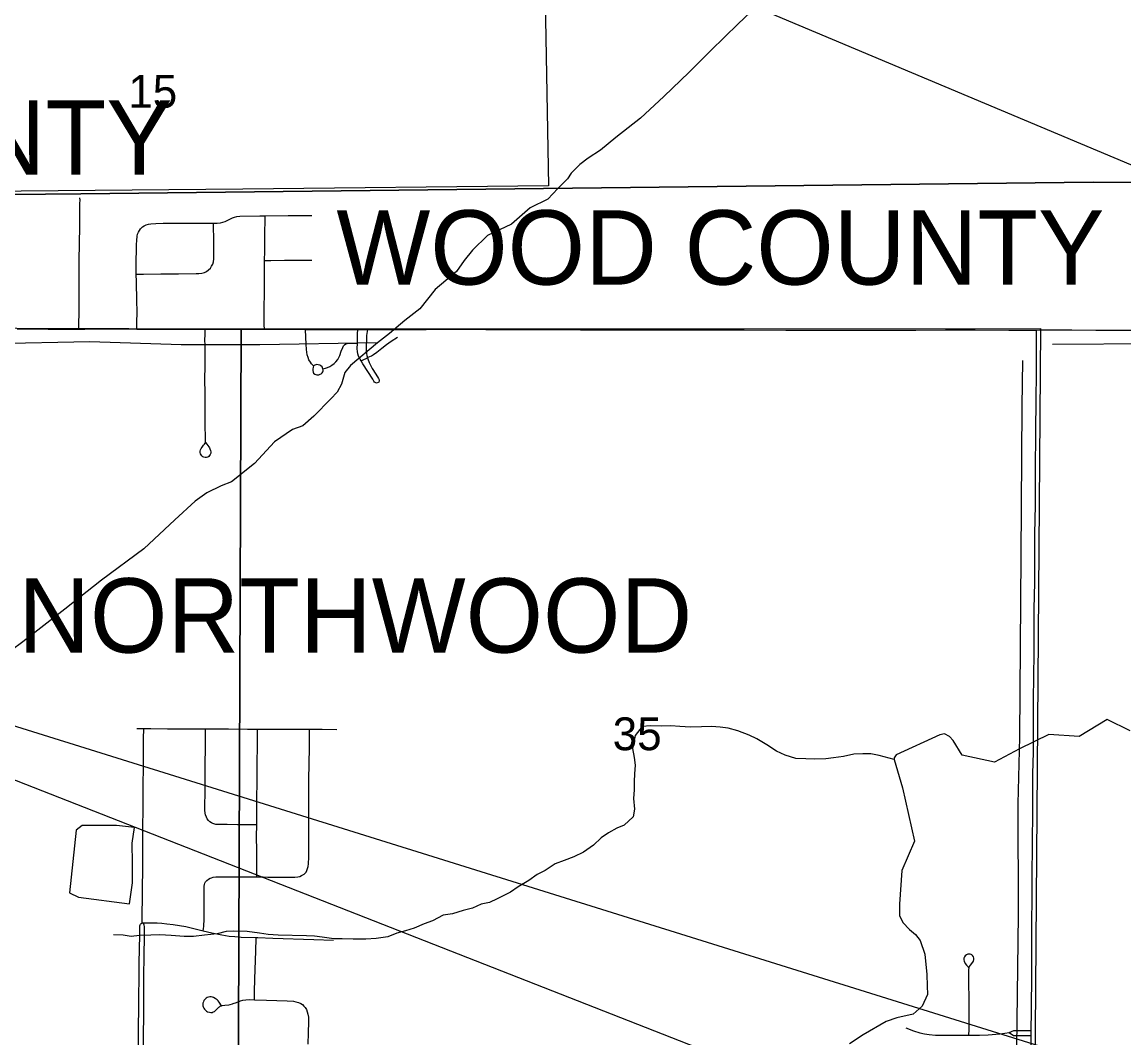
# Model space of a CAD drawing. Extents: x 0 to 40.2, y 0 to 22.
# Drawn here: x 6.486 to 7.889, y 16.354 to 17.647 of the extents above; entities that cross this region are included whole.
import ezdxf

# ---------------------------------------------------------------- set-up
doc = ezdxf.new("R2010")
doc.units = 0
for name, color, linetype in [('GM_X_City_Street', 7, 'Continuous'), ('GM_X_Corporation', 7, 'Continuous'), ('GM_X_County', 7, 'Continuous'), ('GM_X_Minor_Lake', 7, 'Continuous'), ('GM_X_Minor_Lake_Text', 7, 'Continuous'), ('GM_X_Rail_Line', 7, 'Continuous'), ('GM_X_Section', 7, 'Continuous'), ('GM_X_Unincorporated_Location', 7, 'Continuous'), ('GM_X_US_Location', 7, 'Continuous')]:
    doc.layers.add(name, color=color, linetype=linetype)

msp = doc.modelspace()

# ---------------------------------------------------------------- linework, layer by layer
at = {"layer": 'GM_X_Corporation'}
for points in [[(6.1544, 17.4248), (6.5609, 17.4286), (7.8499, 17.4434), (8.1678, 17.4407), (8.7809, 17.439), (8.9, 17.4415), (8.9, 20.9)], [(6.1544, 17.4248), (6.5609, 17.4286), (7.8499, 17.4434), (8.1678, 17.4407), (8.7809, 17.439), (8.9, 17.4415), (8.9, 20.9)], [(6.1544, 17.4248), (6.5609, 17.4286), (7.8499, 17.4434), (8.1678, 17.4407), (8.7809, 17.439), (8.9, 17.4415), (8.9, 20.9)], [(8.7738, 16.2476), (8.7739, 16.404), (8.7812, 17.2357), (8.7808, 17.2416), (8.7804, 17.2472), (8.7798, 17.254), (8.7797, 17.2579), (8.7797, 17.2625), (8.7798, 17.2656), (8.7803, 17.2689), (8.7813, 17.272), (8.7828, 17.2749), (8.7809, 17.439), (8.1678, 17.4407), (7.8499, 17.4434), (6.5609, 17.4286), (6.1544, 17.4248)], [(8.7738, 16.2476), (8.7739, 16.404), (8.7812, 17.2357), (8.7808, 17.2416), (8.7804, 17.2472), (8.7798, 17.254), (8.7797, 17.2579), (8.7797, 17.2625), (8.7798, 17.2656), (8.7803, 17.2689), (8.7813, 17.272), (8.7828, 17.2749), (8.7809, 17.439), (8.1678, 17.4407), (7.8499, 17.4434), (6.5609, 17.4286), (6.1544, 17.4248)], [(8.7738, 16.2476), (8.7739, 16.404), (8.7812, 17.2357), (8.7808, 17.2416), (8.7804, 17.2472), (8.7798, 17.254), (8.7797, 17.2579), (8.7797, 17.2625), (8.7798, 17.2656), (8.7803, 17.2689), (8.7813, 17.272), (8.7828, 17.2749), (8.7809, 17.439), (8.1678, 17.4407), (7.8499, 17.4434), (6.5609, 17.4286), (6.1544, 17.4248)]]:
    msp.add_lwpolyline(points, dxfattribs=at)
for points in [[(6.1533, 17.7006), (7.1511, 17.7217), (7.1565, 17.4389), (6.7672, 17.4346), (6.1554, 17.4291)], [(5.7644, 17.2596), (6.765, 17.2565), (6.7611, 16.2529), (5.7484, 16.2569)], [(6.765, 17.2565), (7.7827, 17.257), (7.775, 16.2496), (7.7689, 16.25), (6.7611, 16.2529)]]:
    msp.add_lwpolyline(points, close=True, dxfattribs=at)
at = {"layer": 'GM_X_Minor_Lake'}
for points in [[(7.4611, 17.7074), (7.4378, 17.6833), (7.3977, 17.645), (7.363, 17.6112), (7.3355, 17.5834), (7.303, 17.5525), (7.2736, 17.5247), (7.242, 17.5004), (7.2226, 17.4842), (7.207, 17.4741), (7.1963, 17.4659), (7.1852, 17.455), (7.1806, 17.4478), (7.1684, 17.4353)], [(7.1684, 17.4353), (7.1553, 17.4216), (7.1329, 17.4106), (7.1094, 17.3901), (7.0786, 17.3754), (7.0597, 17.3567), (7.0489, 17.3436), (7.0393, 17.3297), (7.012, 17.3066), (6.9927, 17.2819), (6.9736, 17.2674), (6.954, 17.2507), (6.9387, 17.2388), (6.9042, 17.2101), (6.8972, 17.2011), (6.8928, 17.186), (6.8874, 17.1759), (6.8793, 17.1673), (6.8574, 17.1456), (6.8436, 17.1333), (6.8303, 17.1286), (6.8073, 17.1127), (6.7819, 17.085), (6.7528, 17.0619), (6.7395, 17.0569), (6.7215, 17.0477), (6.7066, 17.0373), (6.6805, 17.0134), (6.641, 16.9765), (6.5874, 16.9364), (6.5406, 16.8996), (6.487, 16.858), (6.4422, 16.8249)], [(6.9387, 17.2388), (6.7888, 17.2363), (6.6886, 17.2364), (6.5725, 17.2401), (6.4491, 17.2376), (6.2721, 17.2393), (6.1257, 17.2394), (5.9952, 17.2411), (5.6774, 17.2432)], [(8.7602, 17.2356), (8.4984, 17.2357), (8.1515, 17.2375), (7.9283, 17.2376), (7.7978, 17.2367)], [(7.7519, 16.2738), (7.7545, 16.5105), (7.7541, 16.6516), (7.7566, 16.7366), (7.758, 16.9672), (7.7595, 17.1577), (7.7604, 17.2161)], [(7.897, 16.7449), (7.8674, 16.7591), (7.8319, 16.7376), (7.7933, 16.7402), (7.7559, 16.7218), (7.7243, 16.7049), (7.6828, 16.7139), (7.6714, 16.7323), (7.6669, 16.7376), (7.6605, 16.7408), (7.6545, 16.7394), (7.5988, 16.7141), (7.5965, 16.7103), (7.5965, 16.7084), (7.6072, 16.6722), (7.6224, 16.6041), (7.6063, 16.5668), (7.6034, 16.5239), (7.6031, 16.5095), (7.6075, 16.5007), (7.6161, 16.4919), (7.6236, 16.4853), (7.6295, 16.4776), (7.6353, 16.4604), (7.6379, 16.4346), (7.6384, 16.4198), (7.639, 16.4088), (7.632, 16.3941), (7.6208, 16.384), (7.5996, 16.3791), (7.5863, 16.3747), (7.5569, 16.3577), (7.5396, 16.3463)], [(7.5965, 16.7084), (7.5773, 16.7133), (7.5667, 16.7154), (7.5565, 16.7155), (7.5451, 16.7149), (7.5318, 16.7121), (7.5193, 16.7104), (7.5095, 16.7091), (7.4955, 16.7085), (7.4841, 16.7091), (7.4713, 16.7093), (7.4577, 16.7137), (7.4468, 16.7188), (7.4341, 16.727), (7.4217, 16.7344), (7.412, 16.7391), (7.3973, 16.7446), (7.3849, 16.7483), (7.3747, 16.7492), (7.3637, 16.7501), (7.3509, 16.7499), (7.3372, 16.7494), (7.3236, 16.7504), (7.3119, 16.7509), (7.3002, 16.7508), (7.2862, 16.751), (7.2756, 16.7504), (7.2667, 16.7388), (7.2634, 16.7221), (7.2655, 16.7107), (7.2665, 16.7008), (7.2659, 16.6898), (7.2654, 16.68), (7.2652, 16.6697), (7.2647, 16.6584), (7.2656, 16.6451), (7.2643, 16.6352), (7.2528, 16.6244), (7.2433, 16.6208), (7.2329, 16.6149), (7.2234, 16.6086), (7.2134, 16.5989), (7.2008, 16.5904), (7.1886, 16.5841), (7.1764, 16.5794), (7.165, 16.5754), (7.152, 16.5669), (7.1417, 16.5617), (7.1314, 16.5543), (7.1176, 16.5462), (7.108, 16.5391), (7.0909, 16.5307), (7.0814, 16.5263), (7.0707, 16.5238), (7.0597, 16.519), (7.0475, 16.5158), (7.0342, 16.5118), (7.0221, 16.5101), (7.0087, 16.5028), (6.9981, 16.4991), (6.9851, 16.4933), (6.9741, 16.4901), (6.9631, 16.4872), (6.9517, 16.4824), (6.9369, 16.4804), (6.9236, 16.4795), (6.9077, 16.4794), (6.8934, 16.48), (6.8828, 16.4798), (6.868, 16.4819), (6.8582, 16.4832), (6.848, 16.4837), (6.8121, 16.4843), (6.7992, 16.4853), (6.7883, 16.487), (6.7728, 16.4891), (6.7558, 16.4894), (6.746, 16.4892), (6.7346, 16.4863), (6.7183, 16.4847), (6.7042, 16.483), (6.6925, 16.4828), (6.6759, 16.4842), (6.6615, 16.4848), (6.6502, 16.4843), (6.6354, 16.4841), (6.6248, 16.4828), (6.6146, 16.4845), (6.6025, 16.485)]]:
    msp.add_lwpolyline(points, dxfattribs=at)
at = {"layer": 'GM_X_Minor_Lake_Text'}
msp.add_line((6.6268, 16.5511), (6.6266, 16.5761), dxfattribs=at)
msp.add_lwpolyline([(6.6266, 16.5761), (6.6264, 16.6015), (6.6292, 16.6216), (6.6065, 16.6241), (6.5627, 16.6243), (6.5551, 16.6183), (6.5466, 16.5383), (6.5579, 16.533), (6.6229, 16.5242), (6.6268, 16.5511)], dxfattribs=at)
at = {"layer": 'GM_X_Rail_Line'}
msp.add_line((6.7946, 17.2561), (6.8468, 17.2559), dxfattribs=at)
for points in [[(6.4797, 17.2565), (6.5194, 17.2564), (6.5582, 17.2562)], [(6.5582, 17.2562), (6.5661, 17.2562), (6.6027, 17.2566), (6.632, 17.2564)], [(6.632, 17.2564), (6.6407, 17.2563), (6.6805, 17.2564), (6.719, 17.2562)], [(6.719, 17.2562), (6.724, 17.2561), (6.7706, 17.2562), (6.7946, 17.2561)], [(6.8468, 17.2559), (6.8844, 17.2558), (6.9134, 17.2557)], [(6.9134, 17.2557), (6.9257, 17.2557), (6.9603, 17.2557), (7.0007, 17.2558), (7.0455, 17.256), (7.0766, 17.2557), (7.1363, 17.2556), (7.1543, 17.2557), (7.1754, 17.2557), (7.1972, 17.2555), (7.2258, 17.2553), (7.2588, 17.2553), (7.2768, 17.2554), (7.3701, 17.2553), (7.4055, 17.2554), (7.4584, 17.2551), (7.4963, 17.255), (7.5268, 17.2548), (7.5473, 17.2549), (7.6238, 17.2549), (7.6617, 17.2552), (7.6996, 17.2552), (7.7425, 17.255), (7.7778, 17.2551)], [(7.7778, 17.2551), (7.7817, 17.2552), (7.8227, 17.2552), (7.8532, 17.255), (7.8856, 17.255), (7.9098, 17.2549), (7.9359, 17.255), (7.9583, 17.255), (8.0385, 17.2552), (8.0895, 17.2549), (8.1281, 17.2551), (8.1604, 17.2548), (8.1708, 17.2547)]]:
    msp.add_lwpolyline(points, dxfattribs=at)
at = {"layer": 'GM_X_Section'}
for points in [[(9.2177, 17.1988), (9.2181, 16.9107), (4.8427, 18.7497)], [(9.2177, 15.8949), (9.2181, 15.6068), (5.6129, 17.0208)]]:
    msp.add_lwpolyline(points, close=True, dxfattribs=at)
at = {"layer": 'GM_X_Unincorporated_Location'}
for points in [[(6.5582, 17.2562), (6.5583, 17.2623), (6.5587, 17.2777), (6.5587, 17.287), (6.5587, 17.3101), (6.5587, 17.3177), (6.5587, 17.3219), (6.5588, 17.3328), (6.5588, 17.3361), (6.5588, 17.3375), (6.5588, 17.3429), (6.5592, 17.366), (6.5592, 17.3697), (6.5592, 17.3721), (6.5595, 17.38), (6.5596, 17.3925), (6.5596, 17.4043), (6.5597, 17.4092), (6.5598, 17.4161), (6.5599, 17.4205), (6.5598, 17.4235)], [(6.632, 17.2564), (6.6321, 17.2637), (6.6325, 17.2785), (6.6323, 17.2922), (6.6316, 17.3164), (6.6315, 17.3263), (6.6315, 17.3383), (6.6319, 17.3625), (6.6322, 17.3707), (6.6324, 17.3731), (6.6325, 17.3746), (6.6332, 17.3773), (6.6341, 17.3797), (6.6354, 17.382), (6.637, 17.3841), (6.6394, 17.3863), (6.6416, 17.3878), (6.6439, 17.3889), (6.647, 17.39), (6.6502, 17.3905), (6.6564, 17.3908), (6.6658, 17.391), (6.6808, 17.3911), (6.7028, 17.3913), (6.7091, 17.3912), (6.7299, 17.3912), (6.7344, 17.3912), (6.7385, 17.3918), (6.7417, 17.3926), (6.7446, 17.3934), (6.7479, 17.3948), (6.754, 17.3979), (6.7565, 17.3989), (6.7595, 17.3997), (6.7634, 17.4002), (6.7889, 17.4006), (6.7956, 17.4006), (6.825, 17.4008), (6.8551, 17.401)], [(6.7946, 17.2561), (6.7945, 17.2617), (6.7943, 17.2771), (6.7948, 17.3085), (6.7947, 17.3329), (6.7949, 17.3408), (6.7949, 17.3437), (6.7952, 17.3555), (6.7952, 17.3638), (6.7951, 17.3772), (6.7955, 17.3965), (6.7956, 17.4006)], [(6.6315, 17.3263), (6.6393, 17.3263), (6.6405, 17.3263), (6.6628, 17.3266), (6.6852, 17.3267), (6.7076, 17.3269), (6.7113, 17.3272), (6.7149, 17.3275), (6.7182, 17.3285), (6.7207, 17.3298), (6.7234, 17.3318), (6.7258, 17.334), (6.7273, 17.3364), (6.7288, 17.3388), (6.7298, 17.3421), (6.7301, 17.3459), (6.7302, 17.3501), (6.7302, 17.3712), (6.73, 17.3866), (6.7299, 17.3912)], [(6.7949, 17.3437), (6.8029, 17.3438), (6.8202, 17.344), (6.8406, 17.3441), (6.8552, 17.344)], [(6.7196, 17.1119), (6.7215, 17.1096), (6.7238, 17.1063), (6.7247, 17.1049), (6.7253, 17.1038), (6.726, 17.1016), (6.7263, 17.1), (6.7262, 17.0984), (6.7257, 17.0968), (6.7249, 17.0954), (6.7238, 17.0942), (6.7224, 17.0934), (6.7208, 17.0929), (6.7192, 17.0927), (6.7177, 17.0931), (6.7162, 17.0938), (6.7149, 17.0948), (6.7139, 17.0961), (6.7132, 17.0976), (6.7129, 17.0993), (6.713, 17.1009), (6.7134, 17.1025), (6.7141, 17.1041), (6.7152, 17.1058), (6.7162, 17.1072), (6.7172, 17.1083), (6.7184, 17.1096), (6.7192, 17.111), (6.7195, 17.1123), (6.7196, 17.1155), (6.7192, 17.1362), (6.7193, 17.151), (6.7193, 17.1666), (6.7191, 17.1771), (6.7189, 17.1896), (6.719, 17.2119), (6.719, 17.2343), (6.7188, 17.2445), (6.719, 17.2473), (6.719, 17.2512), (6.719, 17.2562)], [(6.8573, 17.2094), (6.856, 17.2108), (6.8546, 17.212), (6.8531, 17.214), (6.8513, 17.2173), (6.8502, 17.2201), (6.8492, 17.2237), (6.8484, 17.2305), (6.8476, 17.2371), (6.8473, 17.246), (6.8468, 17.2559)], [(6.913, 17.2382), (6.9133, 17.2501), (6.9134, 17.2557)], [(6.9257, 17.2557), (6.9248, 17.2481), (6.9247, 17.2473), (6.9245, 17.2444), (6.924, 17.2344), (6.9241, 17.2287), (6.9245, 17.225), (6.925, 17.2226), (6.9258, 17.2199)], [(6.9258, 17.2199), (6.9269, 17.2205), (6.9309, 17.2223), (6.9336, 17.2238), (6.9377, 17.2267), (6.9443, 17.2321), (6.9499, 17.2366), (6.9559, 17.241), (6.9639, 17.2458)], [(7.7708, 16.3335), (7.771, 16.3568), (7.771, 16.3631), (7.7712, 16.3882), (7.7715, 16.4361), (7.7718, 16.4734), (7.7722, 16.5585), (7.7728, 16.6431), (7.7731, 16.6903), (7.7736, 16.717), (7.7739, 16.7319), (7.7738, 16.7698), (7.7739, 16.7842), (7.7745, 16.8438), (7.7748, 16.8998), (7.7754, 16.934), (7.7754, 16.9619), (7.7757, 16.9955), (7.7764, 17.0322), (7.7765, 17.0427), (7.7765, 17.0713), (7.7769, 17.1304), (7.7771, 17.1614), (7.7775, 17.2049), (7.7775, 17.2298), (7.7777, 17.2466), (7.7778, 17.2551)], [(6.8691, 17.2057), (6.8723, 17.2064), (6.8749, 17.2073), (6.8777, 17.2086), (6.8803, 17.2103), (6.8833, 17.2126), (6.8855, 17.2148), (6.8879, 17.2176), (6.8895, 17.2202), (6.8908, 17.2228), (6.8925, 17.2281), (6.8943, 17.2327), (6.8954, 17.2349), (6.8966, 17.2363), (6.8981, 17.2375), (6.9016, 17.2384), (6.9094, 17.2383), (6.913, 17.2382)], [(6.9177, 17.2159), (6.9165, 17.2178), (6.9146, 17.2217), (6.9136, 17.2247), (6.913, 17.2277), (6.9128, 17.2312), (6.913, 17.2382)], [(6.9258, 17.2199), (6.9262, 17.2184), (6.9281, 17.2139), (6.932, 17.2063), (6.9364, 17.1987), (6.9398, 17.1935), (6.9406, 17.1918), (6.9408, 17.1906), (6.9401, 17.1889), (6.9393, 17.1881), (6.9375, 17.1876), (6.9363, 17.1878), (6.9349, 17.1889), (6.9341, 17.1898), (6.9325, 17.1926), (6.9201, 17.212), (6.9177, 17.2159)], [(6.9177, 17.2159), (6.9195, 17.2168), (6.9258, 17.2199)], [(6.8573, 17.2094), (6.8565, 17.2077), (6.8562, 17.2054), (6.8562, 17.2035), (6.8566, 17.2015), (6.8573, 17.2), (6.8586, 17.1989), (6.8601, 17.1983), (6.8613, 17.1981), (6.8626, 17.198), (6.8641, 17.1982), (6.8654, 17.1988), (6.8668, 17.1994), (6.8681, 17.2005), (6.8689, 17.2019), (6.8693, 17.2031), (6.8694, 17.204), (6.8691, 17.2057)], [(6.8691, 17.2057), (6.8687, 17.2069), (6.868, 17.2082), (6.8666, 17.2094), (6.865, 17.2104), (6.8631, 17.2109), (6.8615, 17.2111), (6.8599, 17.2109), (6.8588, 17.2104), (6.8573, 17.2094)], [(6.632, 16.7477), (6.6409, 16.7477), (6.65, 16.7476), (6.6711, 16.7473), (6.6916, 16.7472), (6.7195, 16.7472), (6.7276, 16.7471), (6.7487, 16.7472), (6.773, 16.747), (6.786, 16.7469), (6.802, 16.7469), (6.8326, 16.747), (6.8482, 16.7469), (6.8522, 16.7469), (6.868, 16.7467), (6.8868, 16.7466)], [(6.6389, 16.5003), (6.6391, 16.5096), (6.6396, 16.5339), (6.6397, 16.5793), (6.6399, 16.6079), (6.6402, 16.6589), (6.6406, 16.7148), (6.6408, 16.737), (6.6409, 16.7453), (6.6409, 16.7477)], [(6.7165, 16.4902), (6.7169, 16.4929), (6.7174, 16.4957), (6.7177, 16.4989), (6.7178, 16.5018), (6.7179, 16.5131), (6.718, 16.5235), (6.718, 16.5277), (6.718, 16.5366), (6.718, 16.5436), (6.7181, 16.5468), (6.7183, 16.5489), (6.7188, 16.5506), (6.7198, 16.5523), (6.7214, 16.5541), (6.7233, 16.5557), (6.7254, 16.557), (6.7271, 16.5577), (6.7295, 16.5583), (6.7326, 16.5587), (6.7352, 16.5589), (6.7597, 16.5588), (6.7734, 16.5587), (6.7848, 16.5586), (6.7932, 16.5586), (6.7988, 16.5585), (6.8031, 16.5585), (6.8068, 16.5584), (6.8105, 16.5584), (6.8173, 16.5584), (6.8242, 16.5583), (6.8279, 16.5584), (6.8335, 16.5585), (6.8372, 16.5588), (6.8396, 16.5594), (6.8419, 16.5603), (6.8435, 16.5612), (6.8452, 16.5623), (6.8466, 16.5636), (6.8476, 16.5649), (6.8488, 16.567), (6.8496, 16.5693), (6.8502, 16.572), (6.8507, 16.5752), (6.8508, 16.578), (6.851, 16.5811), (6.8511, 16.6034), (6.8512, 16.6188), (6.8512, 16.6506), (6.8512, 16.6629), (6.8512, 16.676), (6.8513, 16.6829), (6.852, 16.7229), (6.852, 16.7358), (6.8521, 16.7447), (6.8522, 16.7469)], [(6.7848, 16.6251), (6.7829, 16.6251), (6.7738, 16.6251), (6.7603, 16.6252), (6.7474, 16.6253), (6.7394, 16.6253), (6.7359, 16.6253), (6.7341, 16.6254), (6.7326, 16.6256), (6.7313, 16.6259), (6.7301, 16.6263), (6.7289, 16.6269), (6.7274, 16.6276), (6.7253, 16.6289), (6.7234, 16.6306), (6.7219, 16.6325), (6.7207, 16.6347), (6.7197, 16.6376), (6.7192, 16.64), (6.7189, 16.6438), (6.7189, 16.6506), (6.719, 16.6648), (6.7193, 16.6878), (6.7193, 16.6934), (6.7193, 16.7033), (6.7194, 16.7221), (6.7194, 16.7351), (6.7195, 16.7407), (6.7195, 16.7472)], [(6.7848, 16.5586), (6.7848, 16.5606), (6.7848, 16.5788), (6.7849, 16.5919), (6.7847, 16.61), (6.7848, 16.6251), (6.785, 16.6484), (6.7855, 16.69), (6.7856, 16.7037), (6.7857, 16.7254), (6.7859, 16.7421), (6.786, 16.7469)], [(6.6338, 16.2491), (6.6338, 16.2555), (6.6338, 16.2675), (6.6338, 16.2873), (6.6339, 16.3072), (6.6345, 16.3711), (6.6348, 16.3879), (6.6352, 16.4488), (6.6358, 16.4848), (6.6359, 16.4932), (6.6359, 16.4945), (6.6361, 16.4963), (6.6364, 16.4975), (6.637, 16.4985), (6.6377, 16.4994), (6.6389, 16.5003)], [(6.6389, 16.5003), (6.6451, 16.5002), (6.6531, 16.5001), (6.6582, 16.5), (6.6642, 16.4996), (6.6702, 16.499), (6.6784, 16.4982), (6.6864, 16.497), (6.6944, 16.4955), (6.7165, 16.4902), (6.7276, 16.4876), (6.7404, 16.485), (6.7496, 16.4834), (6.757, 16.4826), (6.7651, 16.4821), (6.7843, 16.4816), (6.7862, 16.4816), (6.8054, 16.4808), (6.8576, 16.4791), (6.8824, 16.4783)], [(6.6401, 16.249), (6.6401, 16.2655), (6.6404, 16.3068), (6.6406, 16.336), (6.6406, 16.3547), (6.6409, 16.3846), (6.6412, 16.4039), (6.6412, 16.4331), (6.6416, 16.4568), (6.6418, 16.4847), (6.6418, 16.4937), (6.6418, 16.4957), (6.6415, 16.4974), (6.6409, 16.4986), (6.6403, 16.4993), (6.6389, 16.5003)], [(6.7818, 16.4023), (6.7819, 16.4046), (6.7821, 16.4128), (6.7825, 16.4286), (6.7837, 16.4644), (6.7843, 16.4801), (6.7843, 16.4816)], [(7.6916, 16.357), (7.6917, 16.3645), (7.6918, 16.3757), (7.6921, 16.3887), (7.6919, 16.4055), (7.6916, 16.4216), (7.6913, 16.4347), (7.6915, 16.4403), (7.6919, 16.4427), (7.6925, 16.4445), (7.6934, 16.4461), (7.6966, 16.4499), (7.6975, 16.4515), (7.6979, 16.4533), (7.6979, 16.4552), (7.6973, 16.457), (7.6963, 16.4585), (7.6954, 16.4594), (7.6943, 16.46), (7.6932, 16.4604), (7.6919, 16.4605), (7.6901, 16.4602), (7.6884, 16.4595), (7.6869, 16.4583), (7.6859, 16.4568), (7.6853, 16.455), (7.6852, 16.4531), (7.6856, 16.4513), (7.6866, 16.4485), (7.6886, 16.4464), (7.6902, 16.4447), (7.6911, 16.4427)], [(6.7398, 16.3947), (6.7368, 16.3992), (6.7356, 16.4007), (6.7343, 16.4021), (6.7332, 16.4031), (6.732, 16.404), (6.73, 16.4052), (6.7284, 16.4057), (6.7268, 16.406), (6.7251, 16.406), (6.7234, 16.4057), (6.7218, 16.4051), (6.7204, 16.4042), (6.7187, 16.4027), (6.7177, 16.4013), (6.7169, 16.3998), (6.7164, 16.3981), (6.7162, 16.3964), (6.7163, 16.3947), (6.7167, 16.3931), (6.7174, 16.3915), (6.7183, 16.3901), (6.7195, 16.3888), (6.7208, 16.3878), (6.7223, 16.387), (6.7245, 16.3863), (6.7262, 16.3861), (6.7279, 16.3862), (6.7295, 16.3867), (6.731, 16.3874), (6.7323, 16.3884), (6.7357, 16.392), (6.7366, 16.3928), (6.7373, 16.3933), (6.7382, 16.3939), (6.7391, 16.3943), (6.7401, 16.3947), (6.741, 16.3949), (6.7442, 16.3953), (6.7492, 16.3958), (6.7509, 16.3961), (6.7538, 16.397), (6.755, 16.3973), (6.759, 16.3987), (6.7643, 16.4008), (6.7673, 16.4017), (6.7711, 16.4023), (6.7756, 16.4025), (6.7818, 16.4023), (6.7974, 16.4018), (6.8235, 16.4008), (6.8317, 16.4003), (6.8348, 16.3998), (6.8379, 16.3988), (6.8409, 16.3974), (6.8431, 16.396), (6.845, 16.3942), (6.8467, 16.3922), (6.848, 16.3899), (6.8492, 16.3869), (6.8501, 16.3838), (6.8506, 16.38), (6.8507, 16.3743), (6.8504, 16.36), (6.85, 16.3456)], [(7.6113, 16.3663), (7.6212, 16.3627), (7.6289, 16.3603), (7.6349, 16.3589), (7.6411, 16.3579), (7.6491, 16.3573), (7.659, 16.357), (7.6857, 16.357), (7.6916, 16.357), (7.7049, 16.3571), (7.7161, 16.3576), (7.7308, 16.359), (7.7371, 16.3597), (7.7429, 16.3606)], [(7.7429, 16.3606), (7.7487, 16.363), (7.7634, 16.3631), (7.771, 16.3631)], [(7.7429, 16.3606), (7.7485, 16.3569), (7.7636, 16.3569), (7.771, 16.3568)]]:
    msp.add_lwpolyline(points, dxfattribs=at)

# ---------------------------------------------------------------- texts
at = {"layer": 'GM_X_City_Street'}
for s, p in [('15', (6.6213, 17.5381)), ('35', (7.2381, 16.72))]:
    msp.add_text(s, height=0.04186, rotation=0, dxfattribs=at).set_placement(p)
at = {"layer": 'GM_X_County'}
for s, p in [('LUCAS COUNTY', (5.6856, 17.453)), ('WOOD COUNTY', (6.8863, 17.3129))]:
    msp.add_text(s, height=0.094697, rotation=0, dxfattribs=at).set_placement(p)
at = {"layer": 'GM_X_US_Location'}
msp.add_text('NORTHWOOD', height=0.0947, rotation=0, dxfattribs=at).set_placement((6.4811, 16.8443))

doc.saveas('drawing.dxf')
